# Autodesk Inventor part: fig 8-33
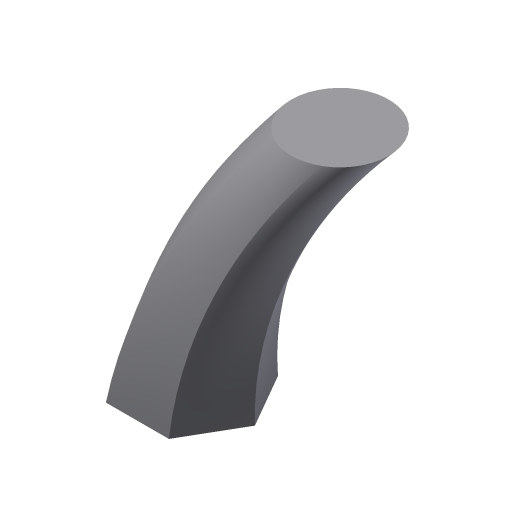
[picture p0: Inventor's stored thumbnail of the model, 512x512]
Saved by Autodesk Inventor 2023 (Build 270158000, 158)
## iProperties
Created: 2001-12
Part Number: fig 8-33
Document SubType Name: Modeling
Designer: CADSoft
Density: 1 g/cm^3
Material: Generic
Appearance: Default
Control State: 0
Master: False
Checked Out: False
Shininess: 77.0
Angle Display Precision: 2
Document Length Units: 11269
Document Angle Units: 11279
Document Time Units: 11290
Document Mass Units: 11283
Document Length Units Precision: 3
Document Angle Units Precision: 2
Density: 0.0
Volumn: 0.0
Area: 0.0
PropertySet Name: Model Information
Author: CADSoft
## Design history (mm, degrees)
workplane "Work Plane3"
workplane "Work Plane4"
sketch "Sketch12"
  geometry: L1 (0, 10.598)-(9.178, -5.299); L2 (9.178, -5.299)-(-9.178, -5.299); L3 (-9.178, -5.299)-(0, 10.598); 1 further point
  constraints: 6 end point, 5 other
workplane "Work Plane5"
workplane "Work Plane6"
workplane "Work Plane7"
sketch "Sketch16"
  geometry: A1 r 72.799 centre (23.007, 110.594) between (0, 41.527) and (70, 54.995); 1 further point
  constraints: 2 point on circle, 1 centre point
loft "Loft5" sketch "Sketch16" dims "d57" = 0, "d58" = 90 deg, "d59" = 0, "d60" = 90 deg, "d61" = 0, "d62" = 90 deg
body "Solid2"
sketch "Sketch1"
  geometry: L1 (19.387, 0)-(9.693, -16.79); L2 (9.693, -16.79)-(-9.693, -16.79); L3 (-9.693, -16.79)-(-19.387, 0); L4 (-19.387, 0)-(-9.693, 16.79); L5 (-9.693, 16.79)-(9.693, 16.79); L6 (9.693, 16.79)-(19.387, 0); 1 further point
  constraints: 12 end point, 11 other
sketch "Sketch2"
  geometry: C1 r 15 at (23.06, 22.535)
  constraints: 1 centre point
